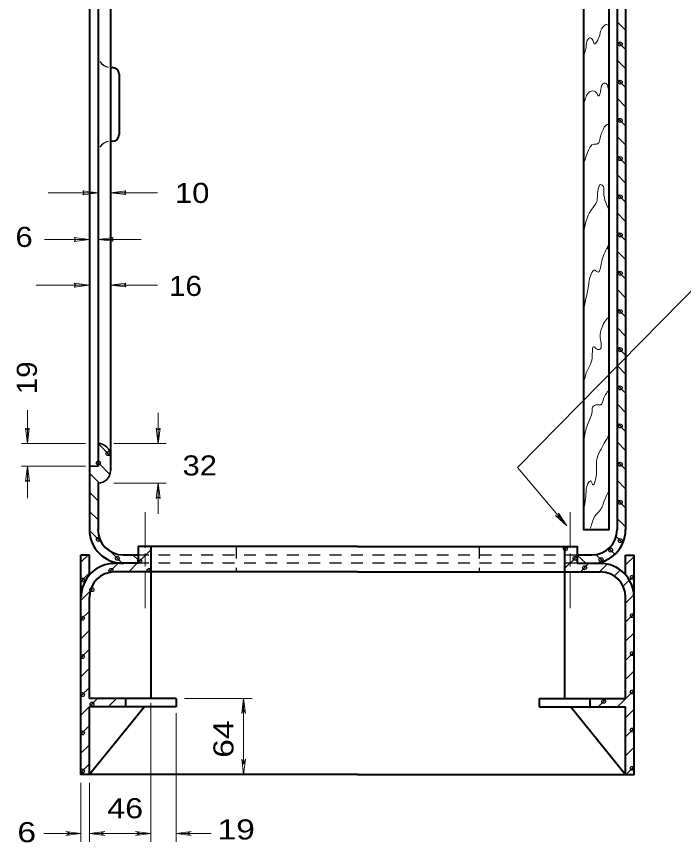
# Model space of a CAD drawing. Extents: x 312583 to 312854, y 144419 to 144597.
# Drawn here: x 312715.36 to 312740.59, y 144454.54 to 144485.79 of the extents above; entities that cross this region are included whole.
import ezdxf
from ezdxf.enums import TextEntityAlignment as Align

# ---------------------------------------------------------------- set-up
doc = ezdxf.new("R2010")
doc.units = 0
doc.header["$LTSCALE"] = 0.3
doc.header["$PDMODE"] = 32
doc.header["$PDSIZE"] = 0.15
doc.linetypes.add('SHORT_DASHED', pattern=[2.7, 1.5, -1.2])
doc.layers.add('1', color=7, linetype='Continuous', lineweight=25)
doc.layers.add('2', color=7, linetype='Continuous', lineweight=13)

msp = doc.modelspace()

# ---------------------------------------------------------------- linework, layer by layer
at = {"layer": '1', "lineweight": 40}
for p, q in [((312718.1211, 144518.1223), (312718.1211, 144466.3723)), ((312736.8124, 144518.1223), (312736.8124, 144466.3723)), ((312738.0851, 144518.1223), (312738.0851, 144466.3723)), ((312738.4071, 144518.1223), (312738.4071, 144466.3723)), ((312718.9184, 144516.6887), (312718.9184, 144468.611)), ((312718.4431, 144516.5277), (312718.4431, 144468.772)), ((312718.9184, 144483.86), (312718.9798, 144483.86)), ((312719.2404, 144483.607), (312719.2404, 144481.3223)), ((312718.9184, 144481.0693), (312718.9798, 144481.0693)), ((312718.4431, 144468.128), (312718.4431, 144466.3723)), ((312720.4364, 144465.736), (312720.4364, 144459.986)), ((312736.0918, 144465.736), (312736.0918, 144459.986)), ((312718.1211, 144465.414), (312717.7991, 144465.414)), ((312718.1211, 144464.6627), (312718.1211, 144465.414)), ((312719.9611, 144465.414), (312719.4014, 144465.414)), ((312737.1268, 144465.414), (312736.5671, 144465.414)), ((312738.4071, 144465.414), (312738.7291, 144465.414)), ((312738.4071, 144464.6627), (312738.4071, 144465.414)), ((312719.9611, 144465.0997), (312719.0794, 144465.0997)), ((312736.5671, 144465.0997), (312737.4488, 144465.0997)), ((312728.2641, 144464.7777), (312719.0794, 144464.7777)), ((312728.2641, 144464.7777), (312737.4488, 144464.7777)), ((312718.1211, 144459.986), (312718.1211, 144463.8193)), ((312738.4071, 144459.986), (312738.4071, 144463.8193)), ((312721.3948, 144459.986), (312718.1211, 144459.986)), ((312719.4781, 144459.986), (312719.4781, 144459.664)), ((312721.3948, 144459.986), (312721.3948, 144459.664)), ((312735.1334, 144459.986), (312738.4071, 144459.986)), ((312735.1334, 144459.986), (312735.1334, 144459.664)), ((312737.0501, 144459.986), (312737.0501, 144459.664)), ((312721.3948, 144459.664), (312718.1211, 144459.664)), ((312720.1988, 144459.664), (312718.1211, 144457.111)), ((312718.1211, 144457.111), (312718.1211, 144459.664)), ((312735.1334, 144459.664), (312738.4071, 144459.664)), ((312736.3294, 144459.664), (312738.4071, 144457.111)), ((312738.4071, 144457.111), (312738.4071, 144459.664))]:
    msp.add_line(p, q, dxfattribs=at)
at = {"layer": '1', "lineweight": 13}
for p, q in [((312738.0851, 144485.5927), (312738.4071, 144485.2707)), ((312738.0851, 144484.8643), (312738.4071, 144484.55)), ((312738.0851, 144484.1437), (312738.4071, 144483.8217)), ((312738.0851, 144483.423), (312738.4071, 144483.101)), ((312738.0851, 144482.7023), (312738.4071, 144482.3803)), ((312738.0851, 144481.974), (312738.4071, 144481.6597)), ((312738.0851, 144481.2533), (312738.4071, 144480.9313)), ((312738.0851, 144480.5327), (312738.4071, 144480.2107)), ((312738.0851, 144479.812), (312738.4071, 144479.49)), ((312738.0851, 144479.0837), (312738.4071, 144478.7617)), ((312738.0851, 144478.363), (312738.4071, 144478.041)), ((312738.0851, 144477.6423), (312738.4071, 144477.3203)), ((312738.0851, 144476.914), (312738.4071, 144476.5997)), ((312738.0851, 144476.1933), (312738.4071, 144475.8713)), ((312738.0851, 144475.4727), (312738.4071, 144475.1507)), ((312738.0851, 144474.7443), (312738.4071, 144474.43)), ((312738.0851, 144474.0237), (312738.4071, 144473.7017)), ((312738.0851, 144473.303), (312738.4071, 144472.981)), ((312738.0851, 144472.5823), (312738.4071, 144472.2603)), ((312738.0851, 144471.854), (312738.4071, 144471.5397)), ((312738.0851, 144471.1333), (312738.4071, 144470.8113)), ((312738.0851, 144470.4127), (312738.4071, 144470.0907)), ((312738.0851, 144469.692), (312738.4071, 144469.37)), ((312718.4431, 144469.6383), (312718.9184, 144469.1553)), ((312718.4431, 144468.9177), (312718.8954, 144468.4577)), ((312738.0851, 144468.9637), (312738.4071, 144468.6493)), ((312718.1211, 144468.5113), (312718.4968, 144468.1357)), ((312738.0851, 144468.243), (312738.4071, 144467.921)), ((312718.1211, 144467.7907), (312718.4431, 144467.4687)), ((312738.0851, 144467.5223), (312738.4071, 144467.2003)), ((312718.1211, 144467.0623), (312718.4431, 144466.748)), ((312738.0851, 144466.794), (312738.4071, 144466.4797)), ((312718.1288, 144466.334), (312718.5198, 144465.943)), ((312738.0468, 144466.1193), (312738.2998, 144465.8587)), ((312736.0918, 144465.6133), (312736.2068, 144465.736)), ((312737.7861, 144465.6517), (312737.9931, 144465.4447)), ((312717.7991, 144465.138), (312718.0751, 144465.414)), ((312718.9184, 144465.5443), (312719.3401, 144465.1227)), ((312719.7694, 144465.414), (312719.9611, 144465.23)), ((312719.9611, 144465.1303), (312720.4364, 144465.6057)), ((312736.0764, 144464.885), (312736.5671, 144465.3757)), ((312736.5748, 144465.414), (312736.8968, 144465.0997)), ((312737.3031, 144465.414), (312737.5254, 144465.1917)), ((312738.4071, 144465.046), (312738.7291, 144465.3603)), ((312718.8571, 144464.747), (312719.2021, 144465.0997)), ((312719.6008, 144464.77), (312719.9228, 144465.0997)), ((312736.6974, 144464.7777), (312737.0118, 144465.0997)), ((312737.4181, 144464.7777), (312737.7094, 144465.069)), ((312717.7991, 144464.4173), (312718.1211, 144464.7393)), ((312720.3138, 144464.7623), (312720.4134, 144464.862)), ((312737.9854, 144464.6243), (312738.2154, 144464.8543)), ((312738.2921, 144464.2103), (312738.7291, 144464.6397)), ((312717.7991, 144463.6967), (312718.1441, 144464.0417)), ((312738.4071, 144463.597), (312738.7291, 144463.919)), ((312717.7991, 144462.976), (312718.1211, 144463.2903)), ((312738.4071, 144462.8763), (312738.7291, 144463.1983)), ((312717.7991, 144462.2477), (312718.1211, 144462.5697)), ((312738.4071, 144462.1557), (312738.7291, 144462.47)), ((312717.7991, 144461.527), (312718.1211, 144461.849)), ((312738.4071, 144461.4273), (312738.7291, 144461.7493)), ((312717.7991, 144460.8063), (312718.1211, 144461.1283)), ((312738.4071, 144460.7067), (312738.7291, 144461.0287)), ((312717.7991, 144460.0857), (312718.1211, 144460.4)), ((312738.0928, 144459.664), (312738.7291, 144460.3003)), ((312717.7991, 144459.3573), (312718.4278, 144459.986)), ((312718.8264, 144459.664), (312719.1484, 144459.986)), ((312737.3644, 144459.664), (312737.6864, 144459.986)), ((312738.4071, 144459.2577), (312738.7291, 144459.5797)), ((312717.7991, 144458.6367), (312718.1211, 144458.9587)), ((312738.4071, 144458.537), (312738.7291, 144458.859)), ((312717.7991, 144457.916), (312718.1211, 144458.2303)), ((312738.4071, 144457.8163), (312738.7291, 144458.1383)), ((312717.7991, 144457.1877), (312718.1211, 144457.5097)), ((312738.4224, 144457.111), (312738.7291, 144457.41))]:
    msp.add_line(p, q, dxfattribs=at)
at = {"layer": '1', "linetype": 'SHORT_DASHED'}
for p, q in [((312723.6641, 144465.736), (312723.6641, 144464.7777)), ((312732.8641, 144465.736), (312732.8641, 144464.7777)), ((312736.5671, 144465.414), (312719.9611, 144465.414)), ((312736.5671, 144465.0997), (312719.9611, 144465.0997))]:
    msp.add_line(p, q, dxfattribs=at)
at = {"layer": '1', "lineweight": 40}
for points in [[(312737.7708, 144518.1223), (312737.7708, 144466.3723), (312736.8124, 144466.3723)], [(312728.2641, 144465.736), (312719.9611, 144465.736), (312719.9611, 144465.0997)], [(312728.2641, 144465.736), (312736.5671, 144465.736), (312736.5671, 144465.0997)], [(312728.2641, 144457.111), (312717.7991, 144457.111), (312717.7991, 144465.414)], [(312728.2641, 144457.111), (312738.7291, 144457.111), (312738.7291, 144465.414)]]:
    msp.add_lwpolyline(points, dxfattribs=at)
at = {"layer": '1'}
for centre, start, end in [((312718.9184, 144484.3417), 211.69761, 259.68185), ((312718.9184, 144480.5902), 100.59153, 148.01047)]:
    msp.add_arc(centre, 0.4792, start, end, dxfattribs=at)
at = {"layer": '1', "lineweight": 40}
for centre, radius, start, end in [((312718.9823, 144483.6083), 0.2556, 0, 90), ((312718.9823, 144481.3249), 0.2556, 270, 0), ((312719.3976, 144466.3749), 1.2778, 180, 270), ((312719.3976, 144466.3749), 0.9583, 180, 270), ((312737.128, 144466.3749), 1.2778, 270, 0), ((312737.128, 144466.3749), 0.9583, 270, 0), ((312719.0782, 144463.8193), 1.2778, 90, 180), ((312737.4475, 144463.8193), 1.2778, 0, 90), ((312719.0782, 144463.8193), 0.9583, 90, 180), ((312737.4475, 144463.8193), 0.9583, 0, 90)]:
    msp.add_arc(centre, radius, start, end, dxfattribs=at)
at = {"layer": '1', "lineweight": 13}
for points in [[(312736.8201, 144484.3583), (312736.9044, 144484.573), (312736.9351, 144484.8413), (312737.0348, 144484.9793), (312737.1421, 144484.941), (312737.2188, 144484.757), (312737.3951, 144484.9947), (312737.4871, 144485.309), (312737.5791, 144485.4317), (312737.6788, 144485.493), (312737.7401, 144485.4623)], [(312736.8201, 144482.5183), (312736.8738, 144482.6487), (312736.9581, 144482.8557), (312737.1038, 144482.9707), (312737.3031, 144482.9017), (312737.3721, 144482.7867), (312737.4564, 144482.9477), (312737.5254, 144483.2237), (312737.5791, 144483.2697), (312737.6711, 144483.2543), (312737.7401, 144483.0703)], [(312736.8201, 144480.2337), (312736.9044, 144480.4867), (312737.0424, 144480.8163), (312737.1728, 144480.9543), (312737.3414, 144480.9697), (312737.4564, 144481.2763), (312737.5408, 144481.4757), (312737.5944, 144481.606), (312737.7554, 144481.7287)], [(312736.8201, 144477.673), (312736.8738, 144477.9107), (312736.9581, 144478.1943), (312737.1191, 144478.4933), (312737.3108, 144478.7923), (312737.3414, 144479.0453), (312737.4871, 144479.4287), (312737.5791, 144479.329), (312737.5791, 144479.1833), (312737.6251, 144478.846), (312737.7554, 144478.5087)], [(312736.8354, 144474.7903), (312736.8891, 144475.0587), (312737.0041, 144475.5877), (312737.1038, 144476.0477), (312737.2418, 144476.1933), (312737.3414, 144476.1243), (312737.4871, 144476.477), (312737.5714, 144476.7453), (312737.7631, 144477.1363), (312737.7248, 144476.983)], [(312736.8278, 144471.969), (312736.9581, 144472.406), (312737.1344, 144472.866), (312737.2111, 144473.2953), (312737.3414, 144473.1957), (312737.4181, 144473.1957), (312737.4411, 144473.6327), (312737.5178, 144474.039), (312737.5944, 144474.2153), (312737.7554, 144474.407)], [(312736.8278, 144469.7303), (312736.8814, 144470.06), (312736.9581, 144470.336), (312737.1344, 144470.8497), (312737.1574, 144471.003), (312737.3414, 144471.1027), (312737.4641, 144471.1027), (312737.5714, 144471.3327), (312737.6174, 144471.44), (312737.7478, 144471.6163)], [(312736.8278, 144467.185), (312736.8661, 144467.369), (312736.9044, 144467.714), (312736.9811, 144468.1203), (312737.0731, 144468.22), (312737.1728, 144468.0667), (312737.2648, 144468.2583), (312737.3031, 144468.657), (312737.3261, 144469.0787), (312737.4794, 144469.4237), (312737.6328, 144469.715), (312737.7324, 144469.8683), (312737.7631, 144469.945)], [(312737.0731, 144466.4337), (312737.1498, 144466.6637), (312737.2494, 144466.8937), (312737.3874, 144467.047), (312737.5024, 144467.2157), (312737.5944, 144467.4457), (312737.7478, 144467.7983)]]:
    msp.add_spline(points, degree=3, dxfattribs=at)
at = {"layer": '1'}
for p in [(312738.2001, 144484.7493), (312738.2001, 144483.308), (312738.2001, 144481.859), (312738.2001, 144480.4177), (312738.2001, 144478.9687), (312738.2001, 144477.5273), (312738.2001, 144476.0783), (312738.2001, 144474.6293), (312738.2001, 144473.188), (312738.2001, 144471.739), (312738.2001, 144470.2977), (312718.8188, 144469.255), (312718.4584, 144468.8947), (312738.2001, 144468.8487), (312738.2001, 144467.4073), (312718.4584, 144466.0043), (312738.2001, 144465.9583), (312736.1301, 144465.6517), (312737.8398, 144465.598), (312719.1791, 144465.2837), (312736.4904, 144465.2913), (312737.4794, 144465.2377), (312720.0148, 144465.1917), (312736.8508, 144464.931), (312718.9338, 144464.8313), (312720.3751, 144464.8313), (312717.8528, 144464.4633), (312738.6601, 144464.5707), (312718.2131, 144464.103), (312738.6601, 144463.1217), (312717.8528, 144463.022), (312717.8528, 144461.573), (312738.6601, 144461.6803), (312738.6601, 144460.2313), (312717.8528, 144460.1317), (312718.2131, 144459.7713), (312737.5714, 144459.871), (312717.8528, 144458.6827), (312738.6601, 144458.79), (312717.8528, 144457.2413), (312738.6601, 144457.341)]:
    msp.add_point(p, dxfattribs=at)
at = {"layer": '2'}
for p, q in [((312718.4431, 144479.122), (312716.5549, 144479.122)), ((312720.6971, 144479.122), (312718.9184, 144479.122)), ((312718.1211, 144477.3587), (312716.4132, 144477.3587)), ((312720.0761, 144477.3587), (312718.4431, 144477.3587)), ((312734.3208, 144468.726), (312741.5198, 144476.0553)), ((312718.1211, 144475.626), (312716.1048, 144475.626)), ((312720.6971, 144475.626), (312718.9184, 144475.626)), ((312715.7751, 144469.6383), (312715.7751, 144470.8957)), ((312720.7201, 144469.6383), (312720.7201, 144470.796)), ((312717.9754, 144469.6383), (312715.5451, 144469.6383)), ((312721.0191, 144469.6383), (312719.0411, 144469.6383)), ((312717.9754, 144468.772), (312715.5451, 144468.772)), ((312715.7751, 144467.5607), (312715.7751, 144468.772)), ((312734.3208, 144468.726), (312736.1838, 144466.518)), ((312721.0191, 144468.128), (312719.0411, 144468.128)), ((312720.7201, 144466.9703), (312720.7201, 144468.128)), ((312720.2218, 144467.0317), (312720.2218, 144465.69)), ((312735.7544, 144466.909), (312735.9308, 144466.817)), ((312736.1838, 144466.518), (312735.7544, 144466.909)), ((312735.8694, 144467.001), (312735.9308, 144466.817)), ((312736.1838, 144466.518), (312735.8694, 144467.001)), ((312736.3064, 144467.0317), (312736.3064, 144465.69)), ((312720.2218, 144464.9847), (312720.2218, 144465.4753)), ((312736.3064, 144464.9847), (312736.3064, 144465.4753)), ((312720.2218, 144463.4053), (312720.2218, 144464.747)), ((312736.3064, 144463.4053), (312736.3064, 144464.747)), ((312721.7168, 144459.986), (312724.2698, 144459.986)), ((312723.9478, 144459.986), (312723.8788, 144459.411)), ((312723.9478, 144459.986), (312724.0244, 144459.411)), ((312723.9478, 144459.986), (312723.9478, 144457.502)), ((312720.4364, 144459.8173), (312720.4364, 144454.558)), ((312721.3948, 144459.4263), (312721.3948, 144454.558)), ((312723.8788, 144459.411), (312723.9478, 144459.595)), ((312724.0244, 144459.411), (312723.9478, 144459.595)), ((312723.8788, 144457.686), (312723.9478, 144457.502)), ((312723.9478, 144457.111), (312723.8788, 144457.686)), ((312724.0244, 144457.686), (312723.9478, 144457.502)), ((312723.9478, 144457.111), (312724.0244, 144457.686)), ((312717.7991, 144456.789), (312717.7991, 144454.558)), ((312718.1211, 144456.789), (312718.1211, 144454.558)), ((312717.7991, 144454.8723), (312716.3961, 144454.8723)), ((312717.2241, 144454.949), (312717.4081, 144454.8723)), ((312717.7991, 144454.8723), (312717.2241, 144454.949)), ((312717.2241, 144454.8033), (312717.4081, 144454.8723)), ((312717.7991, 144454.8723), (312717.2241, 144454.8033)), ((312718.1211, 144454.8723), (312718.6961, 144454.949)), ((312718.1211, 144454.8723), (312720.4364, 144454.8723)), ((312718.1211, 144454.8723), (312718.6961, 144454.8033)), ((312718.6961, 144454.949), (312718.5121, 144454.8723)), ((312718.6961, 144454.8033), (312718.5121, 144454.8723)), ((312719.8614, 144454.949), (312720.0454, 144454.8723)), ((312720.4364, 144454.8723), (312719.8614, 144454.949)), ((312719.8614, 144454.8033), (312720.0454, 144454.8723)), ((312720.4364, 144454.8723), (312719.8614, 144454.8033)), ((312721.3948, 144454.8723), (312721.9698, 144454.949)), ((312721.3948, 144454.8723), (312722.7288, 144454.8723)), ((312721.3948, 144454.8723), (312721.9698, 144454.8033)), ((312721.9698, 144454.949), (312721.7858, 144454.8723)), ((312721.9698, 144454.8033), (312721.7858, 144454.8723))]:
    msp.add_line(p, q, dxfattribs=at)
at = {"layer": '2', "lineweight": 35}
msp.add_line((312718.4431, 144468.772), (312718.1211, 144468.772), dxfattribs=at)
at = {"layer": '2'}
for points in [[(312717.8681, 144479.191), (312718.4431, 144479.122), (312717.8681, 144479.0453), (312717.9218, 144479.122)], [(312719.4934, 144479.053), (312718.9184, 144479.122), (312719.4934, 144479.1987), (312719.4398, 144479.122)], [(312717.5461, 144477.4277), (312718.1211, 144477.3587), (312717.5461, 144477.282), (312717.5998, 144477.3587)], [(312719.0181, 144477.2897), (312718.4431, 144477.3587), (312719.0181, 144477.4353), (312718.9568, 144477.3587)], [(312717.5461, 144475.7027), (312718.1211, 144475.626), (312717.5461, 144475.5493), (312717.5998, 144475.626)], [(312719.4934, 144475.557), (312718.9184, 144475.626), (312719.4934, 144475.7027), (312719.4398, 144475.626)], [(312715.8441, 144470.2133), (312715.7751, 144469.6383), (312715.6984, 144470.2133), (312715.7751, 144470.152)], [(312720.7891, 144470.2133), (312720.7201, 144469.6383), (312720.6434, 144470.2133), (312720.7201, 144470.152)], [(312715.6984, 144468.197), (312715.7751, 144468.772), (312715.8518, 144468.197), (312715.7751, 144468.2507)], [(312720.6434, 144467.553), (312720.7201, 144468.128), (312720.7968, 144467.553), (312720.7201, 144467.6143)]]:
    msp.add_lwpolyline(points, close=True, dxfattribs=at)
at = {"layer": '2', "lineweight": 35}
for centre, start, end in [((312718.4393, 144469.1592), 0, 90), ((312718.4393, 144468.611), 270, 0)]:
    msp.add_arc(centre, 0.4792, start, end, dxfattribs=at)

# ---------------------------------------------------------------- texts
at = {"layer": '2'}
for s, width, p in [('10 ', 1.15, (312722.1688, 144478.737)), ('6 ', 1.15, (312715.8077, 144477.0721)), ('16 ', 1.1, (312721.9081, 144475.218)), ('32 ', 1.15, (312722.4545, 144468.423)), ('46 ', 1.2, (312719.6396, 144455.452)), (' 6 ', 1.25, (312715.7453, 144454.5463)), ('  19 ', 1.25, (312723.4951, 144454.6494))]:
    msp.add_text(s, height=0.76, dxfattribs=dict(at, width=width)).set_placement(p, align=Align.CENTER)
for s, width, p in [('19 ', 1.1, (312716.1311, 144472.273)), (' 64 ', 1.25, (312723.5685, 144458.4472))]:
    msp.add_text(s, height=0.76, rotation=90, dxfattribs=dict(at, width=width)).set_placement(p, align=Align.CENTER)

doc.saveas('drawing.dxf')
